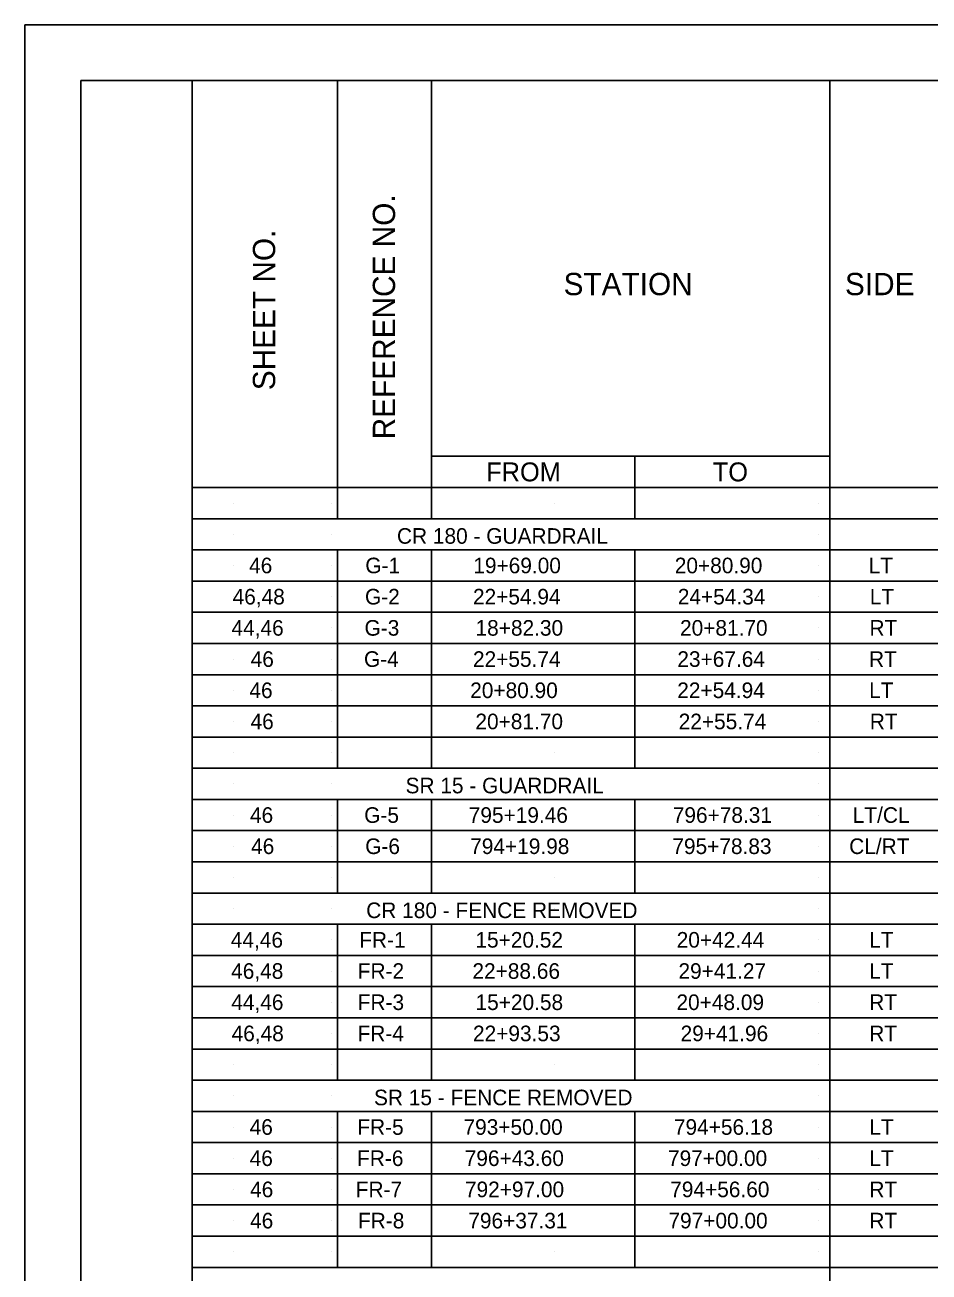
# Model space of a CAD drawing. Extents: x 2073163.9 to 2073197.9, y 634076.5 to 634098.5.
# Drawn here: x 2073163.95 to 2073172.06, y 634087.36 to 634098.55 of the extents above; entities that cross this region are included whole.
import ezdxf

# ---------------------------------------------------------------- set-up
doc = ezdxf.new("R2010")
doc.units = 0
for name, color, linetype in [('SH_Border', 7, 'Continuous'), ('SH_Cut_Line', 7, 'Continuous'), ('SH_Data', 7, 'Continuous'), ('SH_Text', 7, 'Continuous')]:
    doc.layers.add(name, color=color, linetype=linetype)

msp = doc.modelspace()

# ---------------------------------------------------------------- linework, layer by layer
at = {"layer": 'SH_Border'}
msp.add_line((2073165.446, 634094.398), (2073165.446, 634098.05), dxfattribs=at)
for points in [[(2073164.446, 634098.05), (2073165.446, 634098.05), (2073165.446, 634077.05), (2073164.446, 634077.05)], [(2073165.446, 634098.05), (2073197.446, 634098.05), (2073197.446, 634077.05), (2073165.446, 634077.05)]]:
    msp.add_lwpolyline(points, close=True, dxfattribs=at)
at = {"layer": 'SH_Cut_Line'}
msp.add_lwpolyline([(2073163.946, 634076.55), (2073197.946, 634076.55), (2073197.946, 634098.55), (2073163.946, 634098.55)], close=True, dxfattribs=at)
at = {"layer": 'SH_Data'}
for p, q in [((2073166.75, 634094.118), (2073166.75, 634098.05)), ((2073167.595, 634094.118), (2073167.595, 634098.05)), ((2073171.169, 634077.878), (2073171.169, 634098.05)), ((2073165.446, 634094.398), (2073195.946, 634094.398)), ((2073165.821, 634094.258), (2073165.821, 634094.258)), ((2073166.696, 634094.258), (2073166.696, 634094.258)), ((2073168.696, 634094.258), (2073168.696, 634094.258)), ((2073171.071, 634094.258), (2073171.071, 634094.258)), ((2073165.44, 634094.118), (2073195.948, 634094.118)), ((2073165.821, 634093.978), (2073165.821, 634093.978)), ((2073166.696, 634093.978), (2073166.696, 634093.978)), ((2073168.696, 634093.978), (2073168.696, 634093.978)), ((2073171.071, 634093.978), (2073171.071, 634093.978)), ((2073165.45, 634093.838), (2073195.947, 634093.838)), ((2073166.75, 634091.878), (2073166.75, 634093.838)), ((2073167.595, 634091.878), (2073167.595, 634093.838)), ((2073165.821, 634093.698), (2073165.821, 634093.698)), ((2073166.696, 634093.698), (2073166.696, 634093.698)), ((2073168.696, 634093.698), (2073168.696, 634093.698)), ((2073171.071, 634093.698), (2073171.071, 634093.698)), ((2073165.45, 634093.558), (2073195.947, 634093.558)), ((2073165.821, 634093.418), (2073165.821, 634093.418)), ((2073166.696, 634093.418), (2073166.696, 634093.418)), ((2073168.696, 634093.418), (2073168.696, 634093.418)), ((2073171.071, 634093.418), (2073171.071, 634093.418)), ((2073165.447, 634093.278), (2073195.949, 634093.278)), ((2073165.821, 634093.138), (2073165.821, 634093.138)), ((2073166.696, 634093.138), (2073166.696, 634093.138)), ((2073168.696, 634093.138), (2073168.696, 634093.138)), ((2073171.071, 634093.138), (2073171.071, 634093.138)), ((2073165.444, 634092.998), (2073195.947, 634092.998)), ((2073165.821, 634092.858), (2073165.821, 634092.858)), ((2073166.696, 634092.858), (2073166.696, 634092.858)), ((2073168.696, 634092.858), (2073168.696, 634092.858)), ((2073171.071, 634092.858), (2073171.071, 634092.858)), ((2073165.454, 634092.718), (2073195.947, 634092.718)), ((2073165.821, 634092.578), (2073165.821, 634092.578)), ((2073166.696, 634092.578), (2073166.696, 634092.578)), ((2073168.696, 634092.578), (2073168.696, 634092.578)), ((2073171.071, 634092.578), (2073171.071, 634092.578)), ((2073165.45, 634092.438), (2073195.943, 634092.438)), ((2073165.821, 634092.298), (2073165.821, 634092.298)), ((2073166.696, 634092.298), (2073166.696, 634092.298)), ((2073168.696, 634092.298), (2073168.696, 634092.298)), ((2073171.071, 634092.298), (2073171.071, 634092.298)), ((2073165.448, 634092.158), (2073195.943, 634092.158)), ((2073165.821, 634092.018), (2073165.821, 634092.018)), ((2073166.696, 634092.018), (2073166.696, 634092.018)), ((2073168.696, 634092.018), (2073168.696, 634092.018)), ((2073171.071, 634092.018), (2073171.071, 634092.018)), ((2073165.448, 634091.878), (2073195.943, 634091.878)), ((2073165.821, 634091.738), (2073165.821, 634091.738)), ((2073166.696, 634091.738), (2073166.696, 634091.738)), ((2073168.696, 634091.738), (2073168.696, 634091.738)), ((2073171.071, 634091.738), (2073171.071, 634091.738)), ((2073165.448, 634091.598), (2073195.948, 634091.598)), ((2073166.75, 634090.758), (2073166.75, 634091.598)), ((2073167.595, 634090.758), (2073167.595, 634091.598)), ((2073165.821, 634091.458), (2073165.821, 634091.458)), ((2073166.696, 634091.458), (2073166.696, 634091.458)), ((2073168.696, 634091.458), (2073168.696, 634091.458)), ((2073171.071, 634091.458), (2073171.071, 634091.458)), ((2073165.451, 634091.318), (2073195.939, 634091.318)), ((2073165.451, 634091.318), (2073195.944, 634091.318)), ((2073165.821, 634091.178), (2073165.821, 634091.178)), ((2073166.696, 634091.178), (2073166.696, 634091.178)), ((2073168.696, 634091.178), (2073168.696, 634091.178)), ((2073171.071, 634091.178), (2073171.071, 634091.178)), ((2073165.448, 634091.038), (2073195.944, 634091.038)), ((2073165.821, 634090.898), (2073165.821, 634090.898)), ((2073166.696, 634090.898), (2073166.696, 634090.898)), ((2073168.696, 634090.898), (2073168.696, 634090.898)), ((2073171.071, 634090.898), (2073171.071, 634090.898)), ((2073165.445, 634090.758), (2073195.942, 634090.758)), ((2073165.821, 634090.618), (2073165.821, 634090.618)), ((2073166.696, 634090.618), (2073166.696, 634090.618)), ((2073168.696, 634090.618), (2073168.696, 634090.618)), ((2073171.071, 634090.618), (2073171.071, 634090.618)), ((2073165.442, 634090.478), (2073195.946, 634090.478)), ((2073166.75, 634089.078), (2073166.75, 634090.478)), ((2073167.595, 634089.078), (2073167.595, 634090.478)), ((2073165.821, 634090.338), (2073165.821, 634090.338)), ((2073166.696, 634090.338), (2073166.696, 634090.338)), ((2073168.696, 634090.338), (2073168.696, 634090.338)), ((2073171.071, 634090.338), (2073171.071, 634090.338)), ((2073165.442, 634090.198), (2073195.946, 634090.198)), ((2073165.821, 634090.058), (2073165.821, 634090.058)), ((2073166.696, 634090.058), (2073166.696, 634090.058)), ((2073168.696, 634090.058), (2073168.696, 634090.058)), ((2073171.071, 634090.058), (2073171.071, 634090.058)), ((2073165.446, 634089.918), (2073195.946, 634089.918)), ((2073165.821, 634089.778), (2073165.821, 634089.778)), ((2073166.696, 634089.778), (2073166.696, 634089.778)), ((2073168.696, 634089.778), (2073168.696, 634089.778)), ((2073171.071, 634089.778), (2073171.071, 634089.778)), ((2073165.446, 634089.638), (2073195.946, 634089.638)), ((2073165.821, 634089.498), (2073165.821, 634089.498)), ((2073166.696, 634089.498), (2073166.696, 634089.498)), ((2073168.696, 634089.498), (2073168.696, 634089.498)), ((2073171.071, 634089.498), (2073171.071, 634089.498)), ((2073165.446, 634089.358), (2073195.946, 634089.358)), ((2073165.821, 634089.218), (2073165.821, 634089.218)), ((2073166.696, 634089.218), (2073166.696, 634089.218)), ((2073168.696, 634089.218), (2073168.696, 634089.218)), ((2073171.071, 634089.218), (2073171.071, 634089.218)), ((2073165.446, 634089.078), (2073195.946, 634089.078)), ((2073165.821, 634088.938), (2073165.821, 634088.938)), ((2073166.696, 634088.938), (2073166.696, 634088.938)), ((2073168.696, 634088.938), (2073168.696, 634088.938)), ((2073171.071, 634088.938), (2073171.071, 634088.938)), ((2073165.446, 634088.798), (2073195.946, 634088.798)), ((2073166.75, 634087.398), (2073166.75, 634088.798)), ((2073167.595, 634087.398), (2073167.595, 634088.798)), ((2073165.821, 634088.658), (2073165.821, 634088.658)), ((2073166.696, 634088.658), (2073166.696, 634088.658)), ((2073168.696, 634088.658), (2073168.696, 634088.658)), ((2073171.071, 634088.658), (2073171.071, 634088.658)), ((2073165.446, 634088.518), (2073195.946, 634088.518)), ((2073165.821, 634088.378), (2073165.821, 634088.378)), ((2073166.696, 634088.378), (2073166.696, 634088.378)), ((2073168.696, 634088.378), (2073168.696, 634088.378)), ((2073171.071, 634088.378), (2073171.071, 634088.378)), ((2073165.446, 634088.238), (2073195.946, 634088.238)), ((2073165.821, 634088.098), (2073165.821, 634088.098)), ((2073166.696, 634088.098), (2073166.696, 634088.098)), ((2073168.696, 634088.098), (2073168.696, 634088.098)), ((2073171.071, 634088.098), (2073171.071, 634088.098)), ((2073165.446, 634087.958), (2073195.946, 634087.958)), ((2073165.821, 634087.818), (2073165.821, 634087.818)), ((2073166.696, 634087.818), (2073166.696, 634087.818)), ((2073168.696, 634087.818), (2073168.696, 634087.818)), ((2073171.071, 634087.818), (2073171.071, 634087.818)), ((2073165.446, 634087.678), (2073195.946, 634087.678)), ((2073165.821, 634087.538), (2073165.821, 634087.538)), ((2073166.696, 634087.538), (2073166.696, 634087.538)), ((2073168.696, 634087.538), (2073168.696, 634087.538)), ((2073171.071, 634087.538), (2073171.071, 634087.538)), ((2073165.446, 634087.398), (2073195.946, 634087.398))]:
    msp.add_line(p, q, dxfattribs=at)
at = {"layer": 'SH_Text'}
for p, q in [((2073167.595, 634094.678), (2073171.169, 634094.678)), ((2073169.419, 634094.678), (2073169.419, 634094.118)), ((2073169.419, 634093.838), (2073169.419, 634091.878)), ((2073169.419, 634091.598), (2073169.419, 634090.758)), ((2073169.419, 634090.478), (2073169.419, 634089.078)), ((2073169.419, 634088.798), (2073169.419, 634087.398))]:
    msp.add_line(p, q, dxfattribs=at)

# ---------------------------------------------------------------- texts
at = {"layer": 'SH_Data'}
for s, p in [('REFERENCE NO.', (2073167.267, 634094.83)), ('SHEET NO.', (2073166.191, 634095.271))]:
    msp.add_text(s, height=0.2, rotation=90, dxfattribs=at).set_placement(p)
for s, p in [('STATION', (2073168.779, 634096.124)), ('SIDE', (2073171.304, 634096.124))]:
    msp.add_text(s, height=0.2, dxfattribs=at).set_placement(p)
at = {"layer": 'SH_Text'}
for s, p in [('FROM', (2073168.085, 634094.453)), ('TO', (2073170.118, 634094.453))]:
    msp.add_text(s, height=0.17, dxfattribs=at).set_placement(p)
for s, p in [('CR 180 - GUARDRAIL', (2073167.284, 634093.893)), ('46', (2073165.957, 634093.628)), ('G-1', (2073167, 634093.628)), ('19+69.00', (2073167.969, 634093.628)), ('20+80.90', (2073169.777, 634093.628)), ('LT', (2073171.517, 634093.628)), ('46,48', (2073165.809, 634093.348)), ('G-2', (2073166.997, 634093.348)), ('22+54.94', (2073167.966, 634093.348)), ('24+54.34', (2073169.804, 634093.348)), ('LT', (2073171.527, 634093.348)), ('44,46', (2073165.799, 634093.068)), ('G-3', (2073166.993, 634093.068)), ('18+82.30', (2073167.989, 634093.068)), ('20+81.70', (2073169.824, 634093.068)), ('RT', (2073171.524, 634093.068)), ('46', (2073165.971, 634092.788)), ('G-4', (2073166.988, 634092.788)), ('22+55.74', (2073167.966, 634092.788)), ('23+67.64', (2073169.8, 634092.788)), ('RT', (2073171.52, 634092.788)), ('46', (2073165.96, 634092.508)), ('20+80.90', (2073167.941, 634092.508)), ('22+54.94', (2073169.799, 634092.508)), ('LT', (2073171.521, 634092.508)), ('46', (2073165.97, 634092.228)), ('20+81.70', (2073167.988, 634092.228)), ('22+55.74', (2073169.812, 634092.228)), ('RT', (2073171.527, 634092.228)), ('SR 15 - GUARDRAIL', (2073167.361, 634091.653)), ('46', (2073165.965, 634091.388)), ('G-5', (2073166.99, 634091.388)), ('795+19.46', (2073167.928, 634091.388)), ('796+78.31', (2073169.759, 634091.388)), ('LT/CL', (2073171.374, 634091.388)), ('CL/RT', (2073171.342, 634091.108)), ('46', (2073165.975, 634091.108)), ('G-6', (2073166.999, 634091.108)), ('794+19.98', (2073167.941, 634091.108)), ('795+78.83', (2073169.755, 634091.108)), ('CR 180 - FENCE REMOVED', (2073167.008, 634090.533)), ('44,46', (2073165.793, 634090.268)), ('FR-1', (2073166.945, 634090.268)), ('15+20.52', (2073167.988, 634090.268)), ('20+42.44', (2073169.794, 634090.268)), ('LT', (2073171.522, 634090.268)), ('46,48', (2073165.796, 634089.988)), ('FR-2', (2073166.932, 634089.988)), ('22+88.66', (2073167.961, 634089.988)), ('29+41.27', (2073169.81, 634089.988)), ('LT', (2073171.522, 634089.988)), ('44,46', (2073165.797, 634089.708)), ('FR-3', (2073166.932, 634089.708)), ('15+20.58', (2073167.989, 634089.708)), ('20+48.09', (2073169.792, 634089.708)), ('RT', (2073171.522, 634089.708)), ('46,48', (2073165.8, 634089.428)), ('FR-4', (2073166.93, 634089.428)), ('22+93.53', (2073167.966, 634089.428)), ('29+41.96', (2073169.829, 634089.428)), ('RT', (2073171.522, 634089.428)), ('SR 15 - FENCE REMOVED', (2073167.078, 634088.853)), ('46', (2073165.962, 634088.588)), ('FR-5', (2073166.928, 634088.588)), ('793+50.00', (2073167.881, 634088.588)), ('794+56.18', (2073169.769, 634088.588)), ('LT', (2073171.523, 634088.588)), ('46', (2073165.962, 634088.308)), ('FR-6', (2073166.926, 634088.308)), ('796+43.60', (2073167.892, 634088.308)), ('797+00.00', (2073169.716, 634088.308)), ('LT', (2073171.523, 634088.308)), ('46', (2073165.966, 634088.028)), ('FR-7', (2073166.914, 634088.028)), ('792+97.00', (2073167.894, 634088.028)), ('794+56.60', (2073169.736, 634088.028)), ('RT', (2073171.523, 634088.028)), ('46', (2073165.966, 634087.748)), ('FR-8', (2073166.934, 634087.748)), ('796+37.31', (2073167.924, 634087.748)), ('797+00.00', (2073169.72, 634087.748)), ('RT', (2073171.523, 634087.748))]:
    msp.add_text(s, height=0.14, rotation=0.0001, dxfattribs=at).set_placement(p)

doc.saveas('drawing.dxf')
